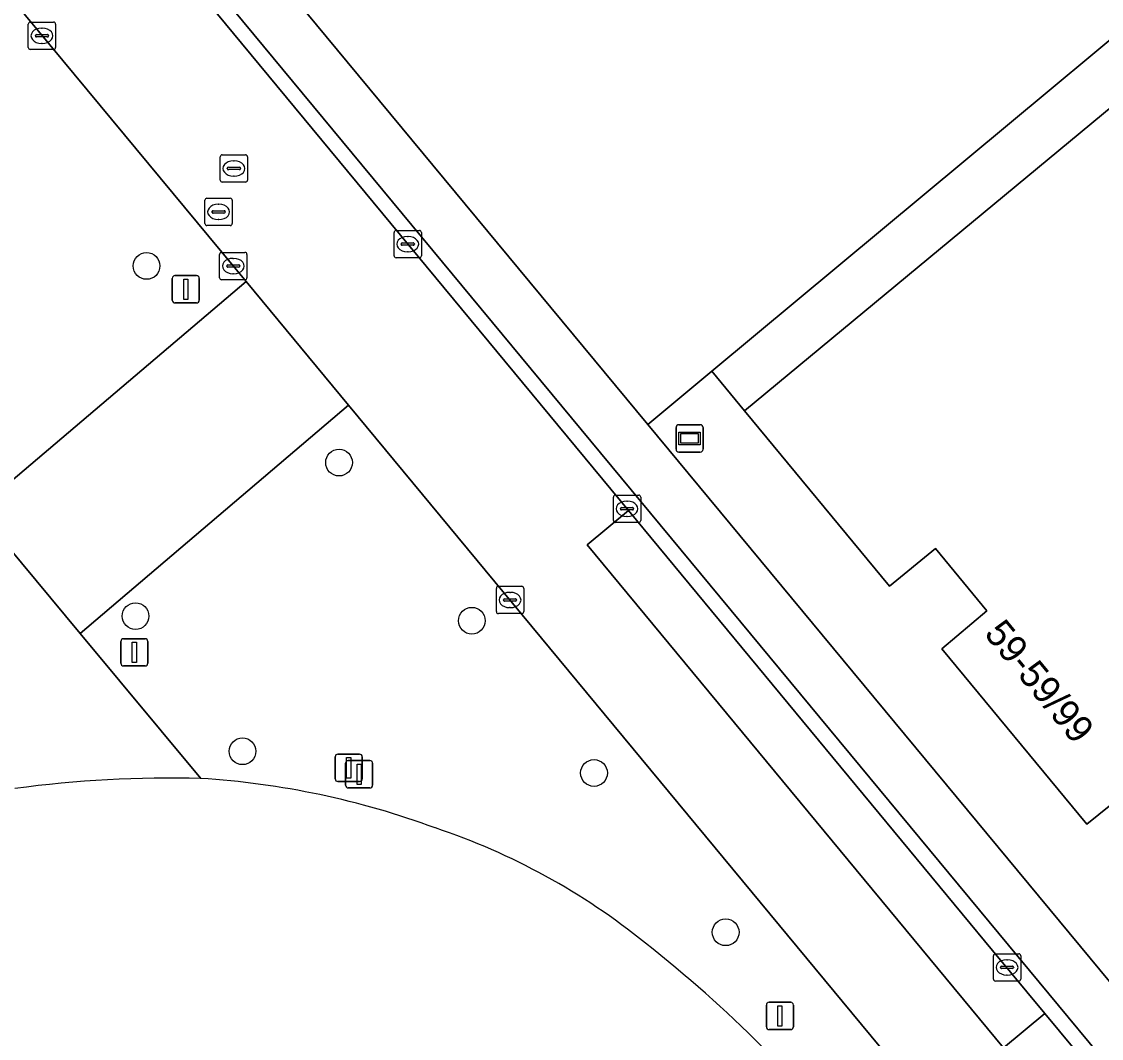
# Model space of a CAD drawing. Extents: x 159489 to 160304, y 383825 to 384531.
# Drawn here: x 159952.57 to 159992.1, y 384255.8 to 384293.03 of the extents above; entities that cross this region are included whole.
import ezdxf

# ---------------------------------------------------------------- set-up
doc = ezdxf.new("R2010")
doc.units = 0
for name, color, linetype in [('IMGEO_Berm_groen', 7, 'Continuous'), ('IMGEO_Boom', 7, 'Continuous'), ('IMGEO_Erf', 7, 'Continuous'), ('IMGEO_Informatiebord', 7, 'Continuous'), ('IMGEO_Kolk', 7, 'Continuous'), ('IMGEO_Lichtmast', 7, 'Continuous'), ('IMGEO_OVBaan_gesloten', 7, 'Continuous'), ('IMGEO_Pand', 7, 'Continuous'), ('IMGEO_Pand_nummerreeks', 7, 'Continuous'), ('IMGEO_Parkeervlak_gesloten', 7, 'Continuous'), ('IMGEO_Rijbaan_lokaal_gesloten', 7, 'Continuous'), ('IMGEO_Rioolput', 7, 'Continuous'), ('IMGEO_Verkeersregelinstallatiepaal', 7, 'Continuous'), ('IMGEO_Voetpad_open', 7, 'Continuous')]:
    doc.layers.add(name, color=color, linetype=linetype)

msp = doc.modelspace()

# ---------------------------------------------------------------- linework, layer by layer
at = {"layer": 'IMGEO_Berm_groen'}
for points in [[(159923.519, 384308.303), (159950.937, 384275.149), (159960.793, 384283.511), (159933.445, 384316.469)], [(159964.53, 384278.991), (159954.711, 384270.626), (159959.123, 384265.32)], [(159983.467, 384251.216), (159985.373, 384248.854), (160015.314, 384212.637), (160035.565, 384188.31), (160037.958, 384190.34), (159964.53, 384278.991)]]:
    msp.add_lwpolyline(points, dxfattribs=at)
for centre, radius, start, end in [((159957.216, 384235.056), 30.324, 69.7462, 86.3952), ((159959.947, 384240.228), 24.539, 50.9477, 71.5469), ((159946.501, 384222.347), 46.903, 37.9888, 51.9544)]:
    msp.add_arc(centre, radius, start, end, dxfattribs=at)
at = {"layer": 'IMGEO_Boom'}
for centre in [(159957.141, 384284.086), (159964.188, 384276.885), (159956.738, 384271.264), (159969.05, 384271.094), (159960.653, 384266.314), (159973.524, 384265.519), (159978.344, 384259.686)]:
    msp.add_circle(centre, 0.489, dxfattribs=at)
at = {"layer": 'IMGEO_Erf'}
for points in [[(159990.837, 384365.638), (160010.691, 384341.649), (160013.944, 384344.349), (159993.239, 384369.301), (159939.01, 384324.365), (159938.439, 384325.04), (159937.427, 384324.203), (159975.49, 384278.275), (159977.835, 384280.227), (160030.58, 384324.136)], [(159993.266, 384265.009), (159991.568, 384263.644), (159986.262, 384270.064), (159987.902, 384271.457), (159986.031, 384273.736), (159984.343, 384272.361), (159979.031, 384278.782), (159977.835, 384280.227), (159975.49, 384278.275), (160035.01, 384206.456)]]:
    msp.add_lwpolyline(points, dxfattribs=at)
at = {"layer": 'IMGEO_Informatiebord'}
for p, q in [((159976.626, 384278.272), (159977.416, 384278.272)), ((159977.416, 384278.272), (159976.626, 384278.272)), ((159976.526, 384277.372), (159976.526, 384278.172)), ((159976.526, 384278.172), (159976.526, 384277.372)), ((159977.516, 384278.172), (159977.516, 384277.372)), ((159977.516, 384277.372), (159977.516, 384278.172)), ((159977.416, 384277.272), (159976.626, 384277.272)), ((159976.626, 384277.272), (159977.416, 384277.272))]:
    msp.add_line(p, q, dxfattribs=at)
for points in [[(159976.627, 384278.004), (159977.415, 384278.004), (159977.415, 384277.54), (159976.627, 384277.54), (159976.627, 384278.004)], [(159976.692, 384277.939), (159976.692, 384277.605), (159977.35, 384277.605), (159977.35, 384277.939), (159976.692, 384277.939)]]:
    msp.add_lwpolyline(points, dxfattribs=at)
for centre, start, end in [((159976.626, 384278.172), 90, 180), ((159976.626, 384278.172), 90, 180), ((159977.416, 384278.172), 0, 90), ((159977.416, 384278.172), 360, 90), ((159976.626, 384277.372), 180, 270), ((159976.626, 384277.372), 180, 270), ((159977.416, 384277.372), 270, 0), ((159977.416, 384277.372), 270, 0)]:
    msp.add_arc(centre, 0.1, start, end, dxfattribs=at)
at = {"layer": 'IMGEO_Kolk'}
for p, q in [((159952.81, 384292.088), (159952.81, 384292.94)), ((159952.885, 384293.014), (159953.737, 384293.014)), ((159953.811, 384292.94), (159953.811, 384292.088)), ((159953.069, 384292.508), (159953.069, 384292.52)), ((159953.507, 384292.471), (159953.109, 384292.471)), ((159953.112, 384292.557), (159953.51, 384292.557)), ((159953.298, 384292.794), (159953.323, 384292.794)), ((159953.553, 384292.52), (159953.553, 384292.508)), ((159953.321, 384292.234), (159953.296, 384292.234)), ((159953.737, 384292.014), (159952.885, 384292.014)), ((159966.278, 384285.384), (159967.13, 384285.384)), ((159966.203, 384284.458), (159966.203, 384285.31)), ((159966.691, 384285.164), (159966.716, 384285.164)), ((159967.204, 384285.31), (159967.204, 384284.458)), ((159959.891, 384284.582), (159960.743, 384284.582)), ((159966.462, 384284.878), (159966.462, 384284.89)), ((159966.9, 384284.841), (159966.502, 384284.841)), ((159966.505, 384284.927), (159966.903, 384284.927)), ((159966.714, 384284.604), (159966.689, 384284.604)), ((159966.946, 384284.89), (159966.946, 384284.878)), ((159959.816, 384283.656), (159959.816, 384284.508)), ((159960.304, 384284.362), (159960.329, 384284.362)), ((159960.817, 384284.508), (159960.817, 384283.656)), ((159967.13, 384284.384), (159966.278, 384284.384)), ((159960.075, 384284.076), (159960.075, 384284.088)), ((159960.513, 384284.039), (159960.115, 384284.039)), ((159960.118, 384284.125), (159960.516, 384284.125)), ((159960.327, 384283.802), (159960.302, 384283.802)), ((159960.559, 384284.088), (159960.559, 384284.076)), ((159960.743, 384283.582), (159959.891, 384283.582)), ((159974.232, 384274.767), (159974.232, 384275.619)), ((159974.307, 384275.693), (159975.159, 384275.693)), ((159974.72, 384275.473), (159974.745, 384275.473)), ((159975.233, 384275.619), (159975.233, 384274.767)), ((159974.491, 384275.187), (159974.491, 384275.199)), ((159974.929, 384275.15), (159974.531, 384275.15)), ((159974.534, 384275.236), (159974.932, 384275.236)), ((159974.975, 384275.199), (159974.975, 384275.187)), ((159975.159, 384274.693), (159974.307, 384274.693)), ((159974.743, 384274.913), (159974.718, 384274.913)), ((159970.024, 384272.354), (159970.876, 384272.354)), ((159969.949, 384271.428), (159969.949, 384272.28)), ((159970.437, 384272.134), (159970.462, 384272.134)), ((159970.95, 384272.28), (159970.95, 384271.428)), ((159970.208, 384271.848), (159970.208, 384271.86)), ((159970.646, 384271.811), (159970.248, 384271.811)), ((159970.251, 384271.897), (159970.649, 384271.897)), ((159970.46, 384271.574), (159970.435, 384271.574)), ((159970.692, 384271.86), (159970.692, 384271.848)), ((159970.876, 384271.354), (159970.024, 384271.354)), ((159988.221, 384258.9), (159989.073, 384258.9)), ((159988.146, 384257.974), (159988.146, 384258.826)), ((159988.634, 384258.68), (159988.659, 384258.68)), ((159989.147, 384258.826), (159989.147, 384257.974)), ((159988.405, 384258.394), (159988.405, 384258.406)), ((159988.843, 384258.357), (159988.445, 384258.357)), ((159988.448, 384258.443), (159988.846, 384258.443)), ((159988.657, 384258.12), (159988.632, 384258.12)), ((159988.889, 384258.406), (159988.889, 384258.394)), ((159989.073, 384257.9), (159988.221, 384257.9))]:
    msp.add_line(p, q, dxfattribs=at)
for points in [[(159952.81, 384292.088), (159952.81, 384292.94)], [(159952.885, 384293.014), (159953.737, 384293.014)], [(159953.811, 384292.94), (159953.811, 384292.088)], [(159953.737, 384292.014), (159952.885, 384292.014)], [(159966.278, 384285.384), (159967.13, 384285.384)], [(159966.203, 384284.458), (159966.203, 384285.31)], [(159967.204, 384285.31), (159967.204, 384284.458)], [(159959.891, 384284.582), (159960.743, 384284.582)], [(159959.816, 384283.656), (159959.816, 384284.508)], [(159960.817, 384284.508), (159960.817, 384283.656)], [(159967.13, 384284.384), (159966.278, 384284.384)], [(159960.743, 384283.582), (159959.891, 384283.582)], [(159974.232, 384274.767), (159974.232, 384275.619)], [(159974.307, 384275.693), (159975.159, 384275.693)], [(159975.233, 384275.619), (159975.233, 384274.767)], [(159975.159, 384274.693), (159974.307, 384274.693)], [(159970.024, 384272.354), (159970.876, 384272.354)], [(159969.949, 384271.428), (159969.949, 384272.28)], [(159970.95, 384272.28), (159970.95, 384271.428)], [(159970.876, 384271.354), (159970.024, 384271.354)], [(159988.221, 384258.9), (159989.073, 384258.9)], [(159988.146, 384257.974), (159988.146, 384258.826)], [(159989.147, 384258.826), (159989.147, 384257.974)], [(159989.073, 384257.9), (159988.221, 384257.9)]]:
    msp.add_lwpolyline(points, dxfattribs=at)
for centre, radius, start, end in [((159952.887, 384292.938), 0.0765, 91.552, 178.448), ((159952.887, 384292.938), 0.0765, 91.552, 178.448), ((159953.735, 384292.938), 0.0765, 1.552, 88.448), ((159953.735, 384292.938), 0.0765, 1.552, 88.448), ((159953.109, 384292.517), 0.0403, 85.8775, 175.7526), ((159953.106, 384292.507), 0.0366, 178.938, 274.7102), ((159953.51, 384292.514), 0.043, 264.8664, 352.4533), ((159953.514, 384292.519), 0.0386, 1.7309, 96.639), ((159952.887, 384292.09), 0.0765, 181.552, 268.448), ((159952.887, 384292.09), 0.0765, 181.552, 268.448), ((159953.735, 384292.09), 0.0765, 271.552, 358.448), ((159953.735, 384292.09), 0.0765, 271.552, 358.448), ((159966.28, 384285.308), 0.0765, 91.552, 178.448), ((159966.28, 384285.308), 0.0765, 91.552, 178.448), ((159967.128, 384285.308), 0.0765, 1.552, 88.448), ((159967.128, 384285.308), 0.0765, 1.552, 88.448), ((159959.893, 384284.506), 0.0765, 91.552, 178.448), ((159959.893, 384284.506), 0.0765, 91.552, 178.448), ((159960.741, 384284.506), 0.0765, 1.552, 88.448), ((159960.741, 384284.506), 0.0765, 1.552, 88.448), ((159966.502, 384284.887), 0.0403, 85.8775, 175.7526), ((159966.499, 384284.877), 0.0366, 178.938, 274.7102), ((159966.903, 384284.884), 0.043, 264.8664, 352.4533), ((159966.907, 384284.889), 0.0386, 1.7309, 96.639), ((159966.28, 384284.46), 0.0765, 181.552, 268.448), ((159966.28, 384284.46), 0.0765, 181.552, 268.448), ((159967.128, 384284.46), 0.0765, 271.552, 358.448), ((159967.128, 384284.46), 0.0765, 271.552, 358.448), ((159960.115, 384284.085), 0.0403, 85.8775, 175.7526), ((159960.112, 384284.075), 0.0366, 178.938, 274.7102), ((159960.516, 384284.082), 0.043, 264.8664, 352.4533), ((159960.52, 384284.087), 0.0386, 1.7309, 96.639), ((159959.893, 384283.658), 0.0765, 181.552, 268.448), ((159959.893, 384283.658), 0.0765, 181.552, 268.448), ((159960.741, 384283.658), 0.0765, 271.552, 358.448), ((159960.741, 384283.658), 0.0765, 271.552, 358.448), ((159974.309, 384275.617), 0.0765, 91.552, 178.448), ((159974.309, 384275.617), 0.0765, 91.552, 178.448), ((159975.157, 384275.617), 0.0765, 1.552, 88.448), ((159975.157, 384275.617), 0.0765, 1.552, 88.448), ((159974.531, 384275.196), 0.0403, 85.8775, 175.7526), ((159974.528, 384275.186), 0.0366, 178.938, 274.7102), ((159974.932, 384275.193), 0.043, 264.8664, 352.4533), ((159974.936, 384275.198), 0.0386, 1.7309, 96.639), ((159974.309, 384274.769), 0.0765, 181.552, 268.448), ((159974.309, 384274.769), 0.0765, 181.552, 268.448), ((159975.157, 384274.769), 0.0765, 271.552, 358.448), ((159975.157, 384274.769), 0.0765, 271.552, 358.448), ((159970.026, 384272.278), 0.0765, 91.552, 178.448), ((159970.026, 384272.278), 0.0765, 91.552, 178.448), ((159970.874, 384272.278), 0.0765, 1.552, 88.448), ((159970.874, 384272.278), 0.0765, 1.552, 88.448), ((159970.248, 384271.857), 0.0403, 85.8775, 175.7526), ((159970.245, 384271.847), 0.0366, 178.938, 274.7102), ((159970.649, 384271.854), 0.043, 264.8664, 352.4533), ((159970.653, 384271.859), 0.0386, 1.7309, 96.639), ((159970.026, 384271.43), 0.0765, 181.552, 268.448), ((159970.026, 384271.43), 0.0765, 181.552, 268.448), ((159970.874, 384271.43), 0.0765, 271.552, 358.448), ((159970.874, 384271.43), 0.0765, 271.552, 358.448), ((159988.223, 384258.824), 0.0765, 91.552, 178.448), ((159988.223, 384258.824), 0.0765, 91.552, 178.448), ((159989.071, 384258.824), 0.0765, 1.552, 88.448), ((159989.071, 384258.824), 0.0765, 1.552, 88.448), ((159988.445, 384258.403), 0.0403, 85.8775, 175.7526), ((159988.442, 384258.393), 0.0366, 178.938, 274.7102), ((159988.846, 384258.4), 0.043, 264.8664, 352.4533), ((159988.85, 384258.405), 0.0386, 1.7309, 96.639), ((159988.223, 384257.976), 0.0765, 181.552, 268.448), ((159988.223, 384257.976), 0.0765, 181.552, 268.448), ((159989.071, 384257.976), 0.0765, 271.552, 358.448), ((159989.071, 384257.976), 0.0765, 271.552, 358.448)]:
    msp.add_arc(centre, radius, start, end, dxfattribs=at)
for centre, major_axis, ratio, start_param, end_param in [((159953.297, 384292.514), (-0.387, 0.002), 0.722429, 4.712389, 7.853982), ((159953.322, 384292.514), (-0.39, 0.002), 0.717154, 1.570796, 4.712389), ((159966.69, 384284.884), (-0.387, 0.002), 0.722429, 4.712389, 7.853982), ((159966.715, 384284.884), (-0.39, 0.002), 0.717154, 1.570796, 4.712389), ((159960.303, 384284.082), (-0.387, 0.002), 0.722429, 4.712389, 7.853982), ((159960.328, 384284.082), (-0.39, 0.002), 0.717154, 1.570796, 4.712389), ((159974.719, 384275.193), (-0.387, 0.002), 0.722429, 4.712389, 7.853982), ((159974.744, 384275.193), (-0.39, 0.002), 0.717154, 1.570796, 4.712389), ((159970.436, 384271.854), (-0.387, 0.002), 0.722429, 4.712389, 7.853982), ((159970.461, 384271.854), (-0.39, 0.002), 0.717154, 1.570796, 4.712389), ((159988.633, 384258.4), (-0.387, 0.002), 0.722429, 4.712389, 7.853982), ((159988.658, 384258.4), (-0.39, 0.002), 0.717154, 1.570796, 4.712389)]:
    msp.add_ellipse(centre, major_axis=major_axis, ratio=ratio, start_param=start_param, end_param=end_param, dxfattribs=at)
at = {"layer": 'IMGEO_Lichtmast'}
for p, q in [((159958.08, 384282.83), (159958.08, 384283.63)), ((159958.08, 384283.63), (159958.08, 384282.83)), ((159958.18, 384283.73), (159958.97, 384283.73)), ((159958.97, 384283.73), (159958.18, 384283.73)), ((159959.07, 384283.63), (159959.07, 384282.83)), ((159959.07, 384282.83), (159959.07, 384283.63)), ((159958.97, 384282.73), (159958.18, 384282.73)), ((159958.18, 384282.73), (159958.97, 384282.73)), ((159964.047, 384265.307), (159964.047, 384266.107)), ((159964.047, 384266.107), (159964.047, 384265.307)), ((159964.147, 384266.207), (159964.937, 384266.207)), ((159964.937, 384266.207), (159964.147, 384266.207)), ((159965.037, 384266.107), (159965.037, 384265.307)), ((159965.037, 384265.307), (159965.037, 384266.107)), ((159964.937, 384265.207), (159964.147, 384265.207)), ((159964.147, 384265.207), (159964.937, 384265.207)), ((159979.835, 384256.221), (159979.835, 384257.021)), ((159979.835, 384257.021), (159979.835, 384256.221)), ((159979.935, 384257.121), (159980.725, 384257.121)), ((159980.725, 384257.121), (159979.935, 384257.121)), ((159980.825, 384257.021), (159980.825, 384256.221)), ((159980.825, 384256.221), (159980.825, 384257.021)), ((159980.725, 384256.121), (159979.935, 384256.121)), ((159979.935, 384256.121), (159980.725, 384256.121))]:
    msp.add_line(p, q, dxfattribs=at)
for points in [[(159958.5, 384283.605), (159958.65, 384283.605), (159958.65, 384282.855), (159958.5, 384282.855), (159958.5, 384283.605)], [(159964.467, 384266.082), (159964.617, 384266.082), (159964.617, 384265.332), (159964.467, 384265.332), (159964.467, 384266.082)], [(159980.255, 384256.996), (159980.405, 384256.996), (159980.405, 384256.246), (159980.255, 384256.246), (159980.255, 384256.996)]]:
    msp.add_lwpolyline(points, dxfattribs=at)
for centre, start, end in [((159958.18, 384283.63), 90, 180), ((159958.18, 384283.63), 90, 180), ((159958.97, 384283.63), 0, 90), ((159958.97, 384283.63), 360, 90), ((159958.18, 384282.83), 180, 270), ((159958.18, 384282.83), 180, 270), ((159958.97, 384282.83), 270, 0), ((159958.97, 384282.83), 270, 0), ((159964.147, 384266.107), 90, 180), ((159964.147, 384266.107), 90, 180), ((159964.937, 384266.107), 0, 90), ((159964.937, 384266.107), 360, 90), ((159964.147, 384265.307), 180, 270), ((159964.147, 384265.307), 180, 270), ((159964.937, 384265.307), 270, 0), ((159964.937, 384265.307), 270, 0), ((159979.935, 384257.021), 90, 180), ((159979.935, 384257.021), 90, 180), ((159980.725, 384257.021), 0, 90), ((159980.725, 384257.021), 360, 90), ((159979.935, 384256.221), 180, 270), ((159979.935, 384256.221), 180, 270), ((159980.725, 384256.221), 270, 0), ((159980.725, 384256.221), 270, 0)]:
    msp.add_arc(centre, 0.1, start, end, dxfattribs=at)
at = {"layer": 'IMGEO_OVBaan_gesloten'}
for centre, radius, start, end in [((159958.03, 384222.826), 42.508, 88.5261, 97.7179), ((159957.216, 384235.056), 30.324, 69.7462, 86.3952), ((159959.947, 384240.228), 24.539, 50.9477, 71.5469), ((159946.501, 384222.347), 46.903, 37.9888, 51.9544)]:
    msp.add_arc(centre, radius, start, end, dxfattribs=at)
at = {"layer": 'IMGEO_Pand'}
msp.add_lwpolyline([(160016.76, 384310.041), (159979.031, 384278.782), (159984.343, 384272.361), (159986.031, 384273.736), (159987.902, 384271.457), (159986.262, 384270.064), (159991.568, 384263.644), (159993.266, 384265.009)], dxfattribs=at)
at = {"layer": 'IMGEO_Parkeervlak_gesloten'}
msp.add_lwpolyline([(159974.782, 384275.132), (159973.268, 384273.877), (159988.52, 384255.456), (159990.035, 384256.71), (159988.119, 384259.024)], close=True, dxfattribs=at)
at = {"layer": 'IMGEO_Rijbaan_lokaal_gesloten'}
for points in [[(160037.81, 384196.565), (160039.018, 384197.587), (160038.858, 384197.779), (160037.343, 384196.516), (160033.227, 384201.454), (159992.986, 384250.055), (159994.505, 384251.312), (159990.035, 384256.71), (159988.52, 384255.456), (159973.268, 384273.877), (159974.782, 384275.132), (159935.565, 384322.496)], [(159933.445, 384316.469), (159960.793, 384283.511), (159964.53, 384278.991), (160037.958, 384190.34), (160042.981, 384184.276), (160044.135, 384182.772), (160048.4, 384186.332), (160043.056, 384192.743), (160041.731, 384191.684)], [(159959.123, 384265.32), (159954.711, 384270.626), (159950.937, 384275.149), (159923.519, 384308.303)]]:
    msp.add_lwpolyline(points, dxfattribs=at)
msp.add_arc((159958.03, 384222.826), 42.508, 88.5261, 97.7179, dxfattribs=at)
at = {"layer": 'IMGEO_Rioolput'}
for p, q in [((159959.913, 384288.154), (159960.765, 384288.154)), ((159959.838, 384287.228), (159959.838, 384288.08)), ((159960.326, 384287.934), (159960.351, 384287.934)), ((159960.839, 384288.08), (159960.839, 384287.228)), ((159960.097, 384287.648), (159960.097, 384287.66)), ((159960.535, 384287.611), (159960.137, 384287.611)), ((159960.14, 384287.697), (159960.538, 384287.697)), ((159960.349, 384287.374), (159960.324, 384287.374)), ((159960.581, 384287.66), (159960.581, 384287.648)), ((159960.765, 384287.154), (159959.913, 384287.154)), ((159959.353, 384286.565), (159960.205, 384286.565)), ((159959.278, 384285.639), (159959.278, 384286.491)), ((159959.766, 384286.345), (159959.791, 384286.345)), ((159960.279, 384286.491), (159960.279, 384285.639)), ((159959.537, 384286.059), (159959.537, 384286.071)), ((159959.975, 384286.022), (159959.577, 384286.022)), ((159959.58, 384286.108), (159959.978, 384286.108)), ((159959.789, 384285.785), (159959.764, 384285.785)), ((159960.021, 384286.071), (159960.021, 384286.059)), ((159960.205, 384285.565), (159959.353, 384285.565))]:
    msp.add_line(p, q, dxfattribs=at)
for points in [[(159959.913, 384288.154), (159960.765, 384288.154)], [(159959.838, 384287.228), (159959.838, 384288.08)], [(159960.839, 384288.08), (159960.839, 384287.228)], [(159960.765, 384287.154), (159959.913, 384287.154)], [(159959.353, 384286.565), (159960.205, 384286.565)], [(159959.278, 384285.639), (159959.278, 384286.491)], [(159960.279, 384286.491), (159960.279, 384285.639)], [(159960.205, 384285.565), (159959.353, 384285.565)]]:
    msp.add_lwpolyline(points, dxfattribs=at)
for centre, radius, start, end in [((159959.915, 384288.078), 0.0765, 91.552, 178.448), ((159959.915, 384288.078), 0.0765, 91.552, 178.448), ((159960.763, 384288.078), 0.0765, 1.552, 88.448), ((159960.763, 384288.078), 0.0765, 1.552, 88.448), ((159960.137, 384287.657), 0.0403, 85.8775, 175.7526), ((159960.134, 384287.647), 0.0366, 178.938, 274.7102), ((159960.538, 384287.654), 0.043, 264.8664, 352.4533), ((159960.542, 384287.659), 0.0386, 1.7309, 96.639), ((159959.915, 384287.23), 0.0765, 181.552, 268.448), ((159959.915, 384287.23), 0.0765, 181.552, 268.448), ((159960.763, 384287.23), 0.0765, 271.552, 358.448), ((159960.763, 384287.23), 0.0765, 271.552, 358.448), ((159959.355, 384286.489), 0.0765, 91.552, 178.448), ((159959.355, 384286.489), 0.0765, 91.552, 178.448), ((159960.203, 384286.489), 0.0765, 1.552, 88.448), ((159960.203, 384286.489), 0.0765, 1.552, 88.448), ((159959.577, 384286.068), 0.0403, 85.8775, 175.7526), ((159959.574, 384286.058), 0.0366, 178.938, 274.7102), ((159959.978, 384286.065), 0.043, 264.8664, 352.4533), ((159959.982, 384286.07), 0.0386, 1.7309, 96.639), ((159959.355, 384285.641), 0.0765, 181.552, 268.448), ((159959.355, 384285.641), 0.0765, 181.552, 268.448), ((159960.203, 384285.641), 0.0765, 271.552, 358.448), ((159960.203, 384285.641), 0.0765, 271.552, 358.448)]:
    msp.add_arc(centre, radius, start, end, dxfattribs=at)
for centre, major_axis, ratio, start_param, end_param in [((159960.325, 384287.654), (-0.387, 0.002), 0.722429, 4.712389, 7.853982), ((159960.35, 384287.654), (-0.39, 0.002), 0.717154, 1.570796, 4.712389), ((159959.765, 384286.065), (-0.387, 0.002), 0.722429, 4.712389, 7.853982), ((159959.79, 384286.065), (-0.39, 0.002), 0.717154, 1.570796, 4.712389)]:
    msp.add_ellipse(centre, major_axis=major_axis, ratio=ratio, start_param=start_param, end_param=end_param, dxfattribs=at)
at = {"layer": 'IMGEO_Verkeersregelinstallatiepaal'}
for p, q in [((159956.199, 384269.537), (159956.199, 384270.337)), ((159956.199, 384270.337), (159956.199, 384269.537)), ((159956.299, 384270.437), (159957.089, 384270.437)), ((159957.089, 384270.437), (159956.299, 384270.437)), ((159957.189, 384270.337), (159957.189, 384269.537)), ((159957.189, 384269.537), (159957.189, 384270.337)), ((159957.089, 384269.437), (159956.299, 384269.437)), ((159956.299, 384269.437), (159957.089, 384269.437)), ((159964.528, 384265.973), (159965.318, 384265.973)), ((159965.318, 384265.973), (159964.528, 384265.973)), ((159964.428, 384265.073), (159964.428, 384265.873)), ((159964.428, 384265.873), (159964.428, 384265.073)), ((159965.418, 384265.873), (159965.418, 384265.073)), ((159965.418, 384265.073), (159965.418, 384265.873)), ((159965.318, 384264.973), (159964.528, 384264.973)), ((159964.528, 384264.973), (159965.318, 384264.973))]:
    msp.add_line(p, q, dxfattribs=at)
for points in [[(159956.619, 384270.312), (159956.769, 384270.312), (159956.769, 384269.562), (159956.619, 384269.562), (159956.619, 384270.312)], [(159964.848, 384265.848), (159964.998, 384265.848), (159964.998, 384265.098), (159964.848, 384265.098), (159964.848, 384265.848)]]:
    msp.add_lwpolyline(points, dxfattribs=at)
for centre, start, end in [((159956.299, 384270.337), 90, 180), ((159956.299, 384270.337), 90, 180), ((159957.089, 384270.337), 0, 90), ((159957.089, 384270.337), 360, 90), ((159956.299, 384269.537), 180, 270), ((159956.299, 384269.537), 180, 270), ((159957.089, 384269.537), 270, 0), ((159957.089, 384269.537), 270, 0), ((159964.528, 384265.873), 90, 180), ((159964.528, 384265.873), 90, 180), ((159965.318, 384265.873), 0, 90), ((159965.318, 384265.873), 360, 90), ((159964.528, 384265.073), 180, 270), ((159964.528, 384265.073), 180, 270), ((159965.318, 384265.073), 270, 0), ((159965.318, 384265.073), 270, 0)]:
    msp.add_arc(centre, 0.1, start, end, dxfattribs=at)
at = {"layer": 'IMGEO_Voetpad_open'}
for points in [[(160035.789, 384205.516), (160035.01, 384206.456), (159975.49, 384278.275), (159937.427, 384324.203), (159935.905, 384322.929), (160048.804, 384186.671), (160050.34, 384187.958), (160045.884, 384193.335), (160045.088, 384194.296)], [(159964.53, 384278.991), (159960.793, 384283.511), (159950.937, 384275.149), (159954.711, 384270.626)]]:
    msp.add_lwpolyline(points, close=True, dxfattribs=at)
for points in [[(160030.58, 384324.136), (159977.835, 384280.227), (159979.031, 384278.782), (160016.76, 384310.041)], [(160048.804, 384186.671), (159935.905, 384322.929)], [(159935.565, 384322.496), (159974.782, 384275.132), (159988.119, 384259.024), (159990.035, 384256.71), (159994.505, 384251.312), (160034.744, 384202.714), (160038.858, 384197.779), (160039.018, 384197.587), (160037.81, 384196.565)]]:
    msp.add_lwpolyline(points, dxfattribs=at)

# ---------------------------------------------------------------- texts
at = {"layer": 'IMGEO_Pand_nummerreeks'}
msp.add_text('59-59/99', height=1, rotation=309.3734, dxfattribs=at).set_placement((159987.779, 384270.604))

doc.saveas('drawing.dxf')
